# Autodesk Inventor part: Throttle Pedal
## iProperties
Shininess: 100.0
Angle Display Precision: 2
Document Length Units: 11269
Document Angle Units: 11279
Document Time Units: 11290
Document Mass Units: 11283
Document Length Units Precision: 3
Document Angle Units Precision: 2
Compacted: True
Created: 2001-08
Part Number: Throttle Pedal
Document SubType Name: Modeling
Designer: Martin Budgell
Density: 0.0
Volumn: 0.0
Area: 0.0
PropertySet Name: Model Information
Control State: 0
Master: False
Checked Out: False
Author: Martin Budgell
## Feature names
1. Derived Body1 [Tagging]
